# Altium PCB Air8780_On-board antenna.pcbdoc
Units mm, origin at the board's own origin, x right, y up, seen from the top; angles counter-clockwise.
Board outline 107.6 x 83.8 mm, 2 copper layers (Top Layer, Bottom Layer); 1 components, 0 nets, 44 pads, 0 vias.
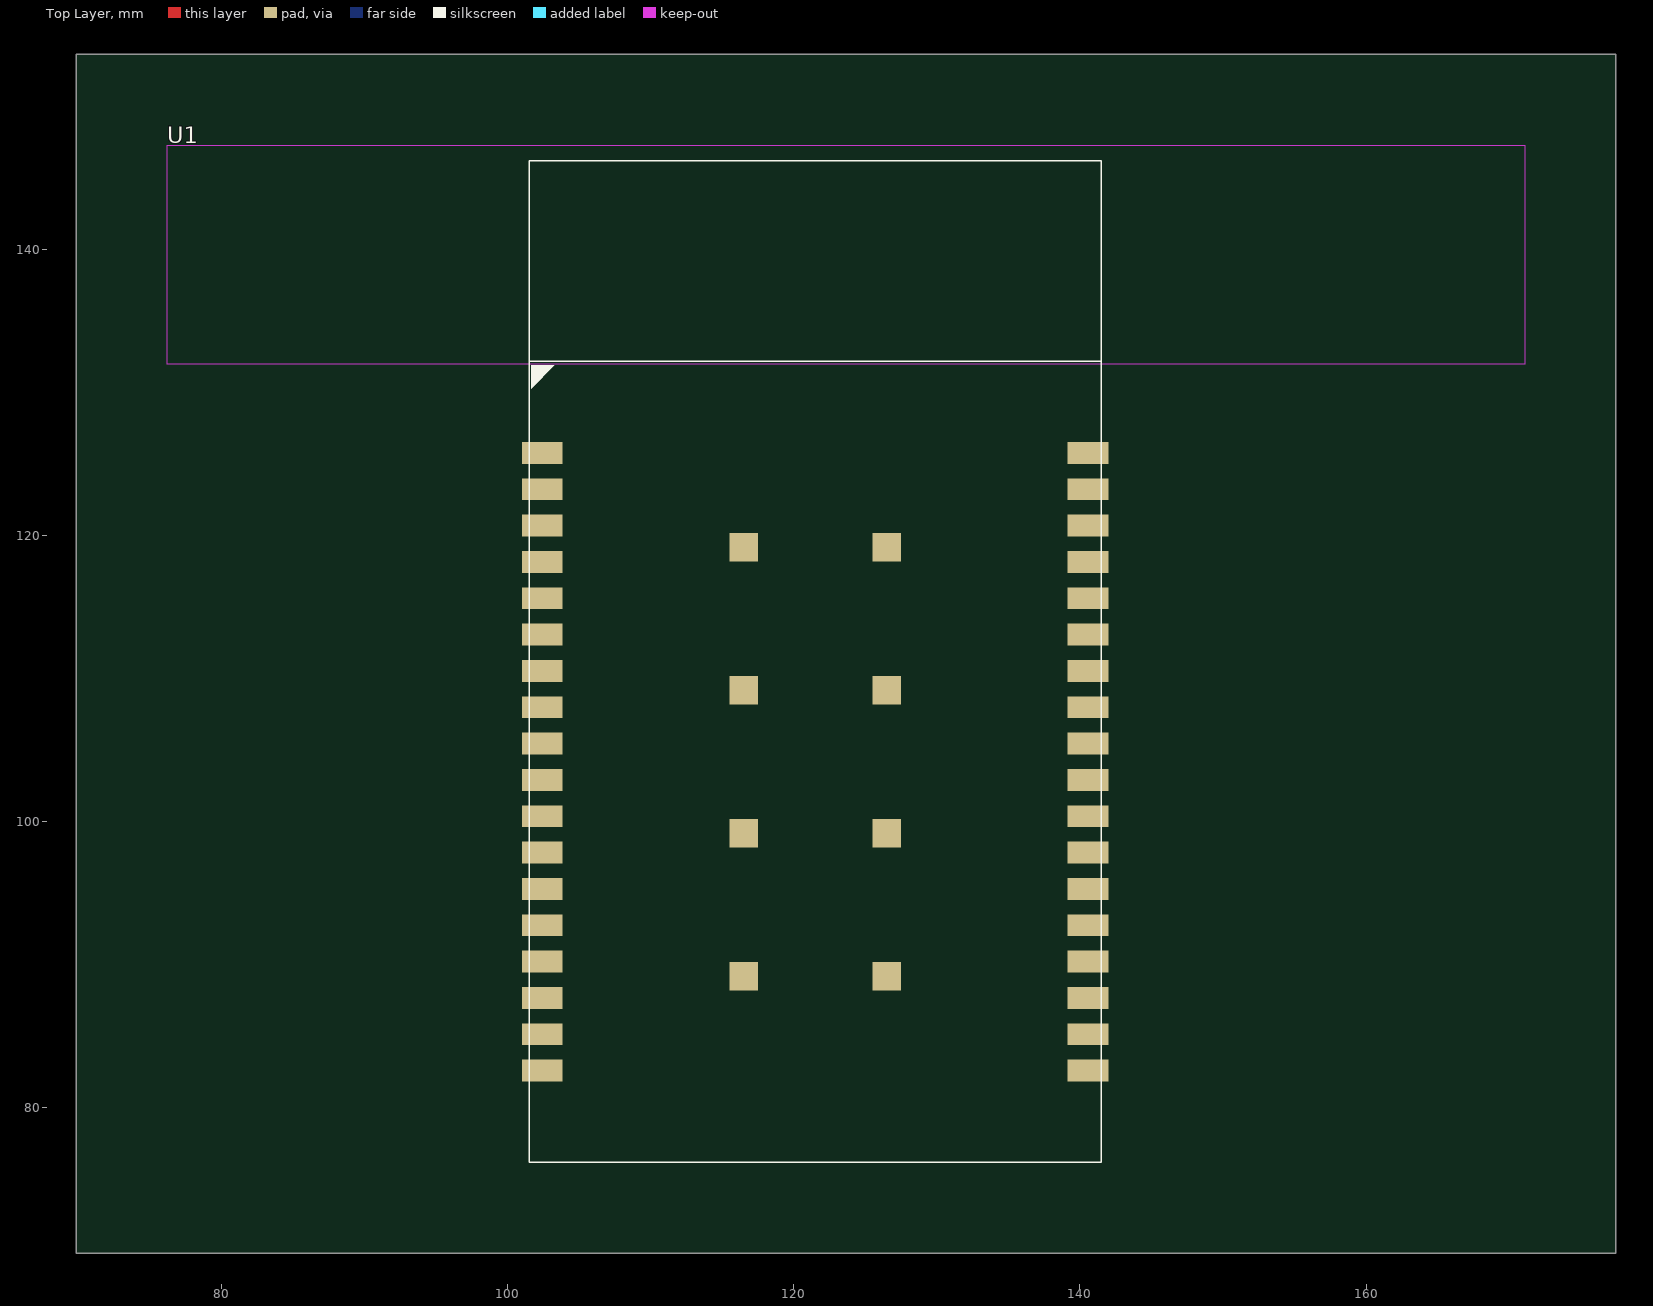
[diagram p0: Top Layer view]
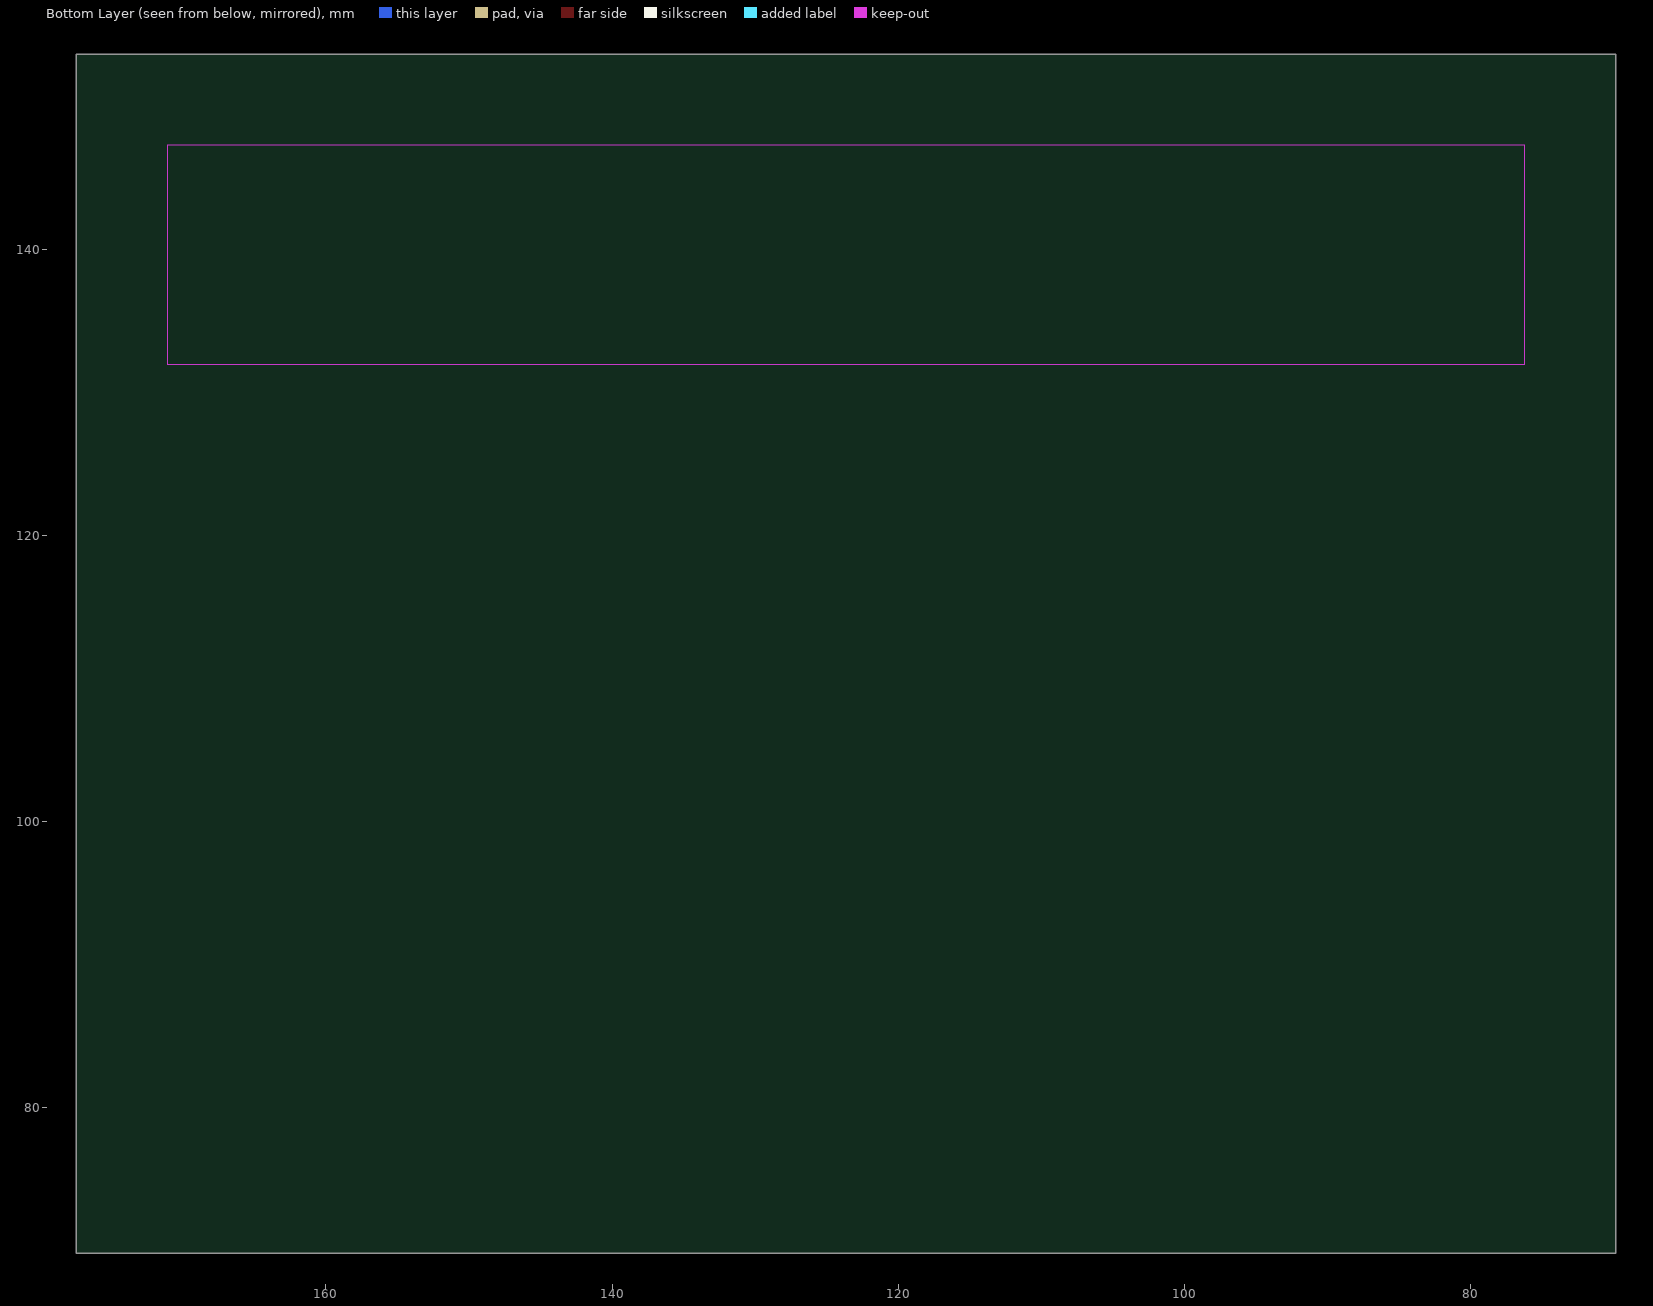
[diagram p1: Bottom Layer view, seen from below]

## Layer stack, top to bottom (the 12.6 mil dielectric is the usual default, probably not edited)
Top Layer: signal copper (thickness not stored)
Dielectric: dielectric 0.32, FR-4, Dk 4.8
Bottom Layer: signal copper (thickness not stored)

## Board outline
177.45,69.85 69.85,69.85 69.85,153.65 177.45,153.65

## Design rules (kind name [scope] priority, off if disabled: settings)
BoardOutlineClearance copperThickness1oz [All] p0: genericclearance=0.254 ignorepadtopadclearanceinfootprint=FALSE except(0: Arc-SplitContinuation Track-SplitContinuation SMDPad-SplitContinuation THPad-SplitContinuation Via-SplitContinuation Fill-SplitContinuation Poly-SplitContinuation Region-SplitContinuation Text-SplitContinuation; 0.152: Track-CutoutEdge SMDPad-CutoutEdge THPad-CutoutEdge Via-CutoutEdge Region-CutoutEdge; 0.3: Track-OutlineEdge SMDPad-OutlineEdge THPad-OutlineEdge Via-OutlineEdge Fill-OutlineEdge Region-OutlineEdge Poly-OutlineEdge Text-OutlineEdge Fill-CutoutEdge)
BoardOutlineClearance copperThickness2oz [All] p0: genericclearance=0.254 ignorepadtopadclearanceinfootprint=FALSE except(0: Arc-SplitContinuation Track-SplitContinuation SMDPad-SplitContinuation THPad-SplitContinuation Via-SplitContinuation Fill-SplitContinuation Poly-SplitContinuation Region-SplitContinuation Text-SplitContinuation; 0.152: Track-CutoutEdge SMDPad-CutoutEdge THPad-CutoutEdge Via-CutoutEdge Region-CutoutEdge; 0.3: Track-OutlineEdge SMDPad-OutlineEdge THPad-OutlineEdge Via-OutlineEdge Fill-OutlineEdge Region-OutlineEdge Poly-OutlineEdge Text-OutlineEdge Fill-CutoutEdge)
Clearance copperThickness1oz [All] p1: gap=0.178 ignorepadtopadclearanceinfootprint=FALSE except(0.102: Track-Track; 0.152: Track-SMDPad SMDPad-SMDPad Track-THPad SMDPad-THPad THPad-THPad Track-Via SMDPad-Via THPad-Via Via-Via SMDPad-Fill THPad-Fill Via-Fill Fill-Fill Track-Region SMDPad-Region THPad-Region Via-Region Region-Region Track-Poly SMDPad-Poly THPad-Poly Via-Poly Fill-Poly Region-Poly Poly-Poly Track-Text SMDPad-Text THPad-Text Via-Text Fill-Text Region-Text Poly-Text Text-Text; 0.175: Track-Hole SMDPad-Hole THPad-Hole Via-Hole Fill-Hole Region-Hole Poly-Hole Text-Hole Sheet-Hole; 0.3: Track-Fill Fill-Region Track-Sheet SMDPad-Sheet THPad-Sheet Via-Sheet Fill-Sheet Region-Sheet Poly-Sheet Text-Sheet)
Clearance copperThickness2oz [All] p1: gap=0.178 ignorepadtopadclearanceinfootprint=FALSE except(0.152: Track-SMDPad SMDPad-SMDPad Track-THPad SMDPad-THPad THPad-THPad Track-Via SMDPad-Via THPad-Via Via-Via SMDPad-Fill THPad-Fill Via-Fill Fill-Fill Track-Region SMDPad-Region THPad-Region Via-Region Region-Region Track-Poly SMDPad-Poly THPad-Poly Via-Poly Fill-Poly Region-Poly Poly-Poly Track-Text SMDPad-Text THPad-Text Via-Text Fill-Text Region-Text Poly-Text Text-Text; 0.175: Track-Hole SMDPad-Hole THPad-Hole Via-Hole Fill-Hole Region-Hole Poly-Hole Text-Hole Sheet-Hole; 0.203: Track-Track; 0.3: Track-Fill Fill-Region Track-Sheet SMDPad-Sheet THPad-Sheet Via-Sheet Fill-Sheet Region-Sheet Poly-Sheet Text-Sheet)
DiffPairsRouting differentialPair [All] p1: maxuncoupledlength=10 minlimit=6 maxlimit=6 mostfreqgap=6 toplayer_minwidth=5 toplayer_prefwidth=10 toplayer_maxwidth=100 bottomlayer_minwidth=5 bottomlayer_prefwidth=10 bottomlayer_maxwidth=100
PasteMaskExpansion pasteMaskExpansion [All] p1: expansion=0
PlaneConnect innerPlane [All] p1: planeconnectstyle=Relief reliefexpansion=0.508 reliefentries=4 reliefconductorwidth=0.254 reliefairgap=0.254
PolygonConnect copperRegion [All] p1: connectstyle=Relief reliefentries=4 reliefconductorwidth=10 polygonreliefangle="90 Angle" airgapwidth=10
RoutingVias viaSize [All] p1: viastyle="Through Hole" holewidth=12.0078 minholewidth=11.811 maxholewidth=248.0314 width=24.0158 minwidth=19.685 maxwidth=393.7008
SolderMaskExpansion solderMaskExpansion [All] p1: useseparateexpansions=TRUE expansion=2 expansionbottom=2
Width copperThickness1oz [All] p1: maxlimit=100 minlimit=5 preferedwidth=10
Width copperThickness2oz [All] p1: maxlimit=100 minlimit=8 preferedwidth=10

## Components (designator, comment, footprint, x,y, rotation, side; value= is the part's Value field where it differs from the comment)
U1 "AIR8780_ON-BOARD_ANTENNA" AIR8780_ON-BOARD_ANTENNA 121.5,104.2 r0 top

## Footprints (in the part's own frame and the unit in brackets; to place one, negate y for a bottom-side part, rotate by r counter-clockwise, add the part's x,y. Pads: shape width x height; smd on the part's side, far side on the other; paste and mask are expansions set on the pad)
AIR8780_ON-BOARD_ANTENNA [mm]
  rect 2.85x1.524 smd: 1(-19.075,21.59) 2(-19.075,19.05) 3(-19.075,16.51) 4(-19.075,13.97) 5(-19.075,11.43) 6(-19.075,8.89) 7(-19.075,6.35) 8(-19.075,3.81) 9(-19.075,1.27) 10(-19.075,-1.27) 11(-19.075,-3.81) 12(-19.075,-6.35) 13(-19.075,-8.89) 14(-19.075,-11.43) 15(-19.075,-13.97) 16(-19.075,-16.51) 17(-19.075,-19.05) 18(-19.075,-21.59) 19(19.075,-21.59) 20(19.075,-19.05) 21(19.075,-16.51) 22(19.075,-13.97) 23(19.075,-11.43) 24(19.075,-8.89) 25(19.075,-6.35) 26(19.075,-3.81) 27(19.075,-1.27) 28(19.075,1.27) 29(19.075,3.81) 30(19.075,6.35) 31(19.075,8.89) 32(19.075,11.43) 33(19.075,13.97) 34(19.075,16.51) 35(19.075,19.05) 36(19.075,21.59)
  rect 2x2 smd: 37(-5,15) 38(-5,5) 39(-5,-5) 40(-5,-15) 41(5,-15) 42(5,-5) 43(5,5) 44(5,15)
  Board Outline Layer region: -45.3,43.1 49.6,43.1 49.6,27.8 -45.3,27.8
  silkscreen extent -20,-28 20,42

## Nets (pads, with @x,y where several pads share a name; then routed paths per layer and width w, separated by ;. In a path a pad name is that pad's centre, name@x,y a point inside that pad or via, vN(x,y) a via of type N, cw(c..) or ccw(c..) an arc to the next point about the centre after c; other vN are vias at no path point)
pads on no net: U1.1 U1.2 U1.3 U1.4 U1.5 U1.6 U1.7 U1.8 U1.9 U1.10 U1.11 U1.12 U1.13 U1.14 U1.15 U1.16 U1.17 U1.18 U1.19 U1.20 U1.21 U1.22 U1.23 U1.24 U1.25 U1.26 U1.27 U1.28 U1.29 U1.30 U1.31 U1.32 U1.33 U1.34 U1.35 U1.36 U1.37 U1.38 U1.39 U1.40 U1.41 U1.42 U1.43 U1.44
